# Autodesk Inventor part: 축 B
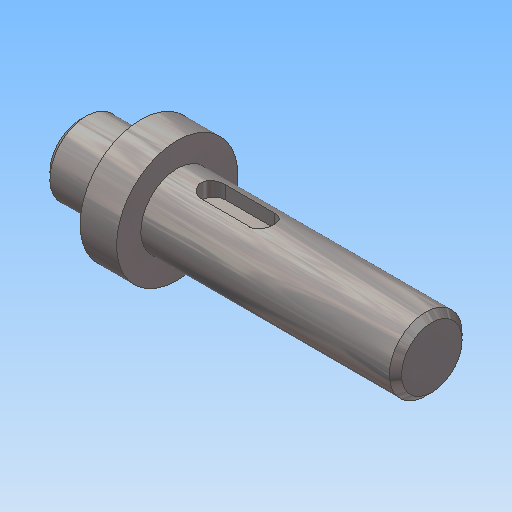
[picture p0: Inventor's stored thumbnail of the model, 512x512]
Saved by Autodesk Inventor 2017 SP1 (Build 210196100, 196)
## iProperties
Created: 2020-04
Part Number: 축 B
Material: 강철, 연강
Document SubType Name: Modeling
Designer: mduedu
Density: 7.86 g/cm^3
Mass: 57.2004 g
Surface Area: 29.0657 cm^2
Volume: 7.2774 cm^3
Appearance: 강철
Author: mduedu
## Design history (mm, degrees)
revolve "회전1" stored, may be unused: angle "d11" = 90 deg
sketch "스케치3"
  geometry: L1 (0, -6)-(0, 6) reference; L2 (0, 6)-(10, 6) reference; L3 (10, 6)-(10, 10) reference; L4 (10, 10)-(16, 10) reference; L5 (16, 10)-(16, 6) reference; L6 (16, 6)-(58, 6) reference; L7 (58, 6)-(58, -6) reference; L8 (58, -6)-(16, -6) reference; L9 (16, -6)-(16, -10) reference; L10 (16, -10)-(10, -10) reference; L11 (10, -10)-(10, -6) reference; L12 (10, -6)-(0, -6) reference; L13 (20, 6)-(32, 6); L14 (32, 6)-(32, 3.5); L15 (32, 3.5)-(20, 3.5); L16 (20, 3.5)-(20, 6); 1 further point
  constraints: 8 end point, 2 parallel, 1 horizontal, 1 perpendicular, 1 point on line
  dimensions: "d17" = 12 distance of L14.end L15.end; "d18" = 2.5 distance of L13.end L14.end; "d19" = 4 distance from line of L16 L4.end
extrude "돌출2" cut sketch "스케치3" stored distance "d20" = 4; taper "d21" = 0 deg
fillet "모깎기2" dims "d22" = 2
chamfer "모따기1" distance "d23" = 1; stored, may be unused: second distance "d24" = 2, angle "d25" = 45 deg
chamfer "모따기2" distance "d26" = 1; stored, may be unused: second distance "d27" = 2, angle "d28" = 45 deg
fillet "모깎기3" dims "d29" = 0.3
node "솔리드1"
sketch "스케치1"
  geometry: L1 (0, 0)-(10, 0); L2 (10, 0)-(10, 6); L3 (10, 6)-(0, 6); L4 (0, 6)-(0, 0); L5 (10, 0)-(16, 0); L6 (16, 0)-(16, 10); L7 (16, 10)-(10, 10); L8 (10, 10)-(10, 0); L9 (16, 0)-(58, 0); L10 (58, 0)-(58, 6); L11 (58, 6)-(16, 6); L12 (16, 6)-(16, 0); L13 (58, 0)-(58, 0); L14 (58, 5)-(58, 0)
  constraints: 28 end point, 6 parallel, 4 horizontal, 3 perpendicular
  dimensions: "d2" = 10 distance of L2.end L3.end; "d3" = 6 distance of L6.end L7.end; "d7" = 12 diameter of L11 L9; "d8" = 12 diameter of L3 L1; "d9" = 20 diameter of L7 L5; "d36" = 58 distance between parallel lines of L10 L4
node "절단 모서리 투영2"
